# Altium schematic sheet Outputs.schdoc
size 345 x 187 mm
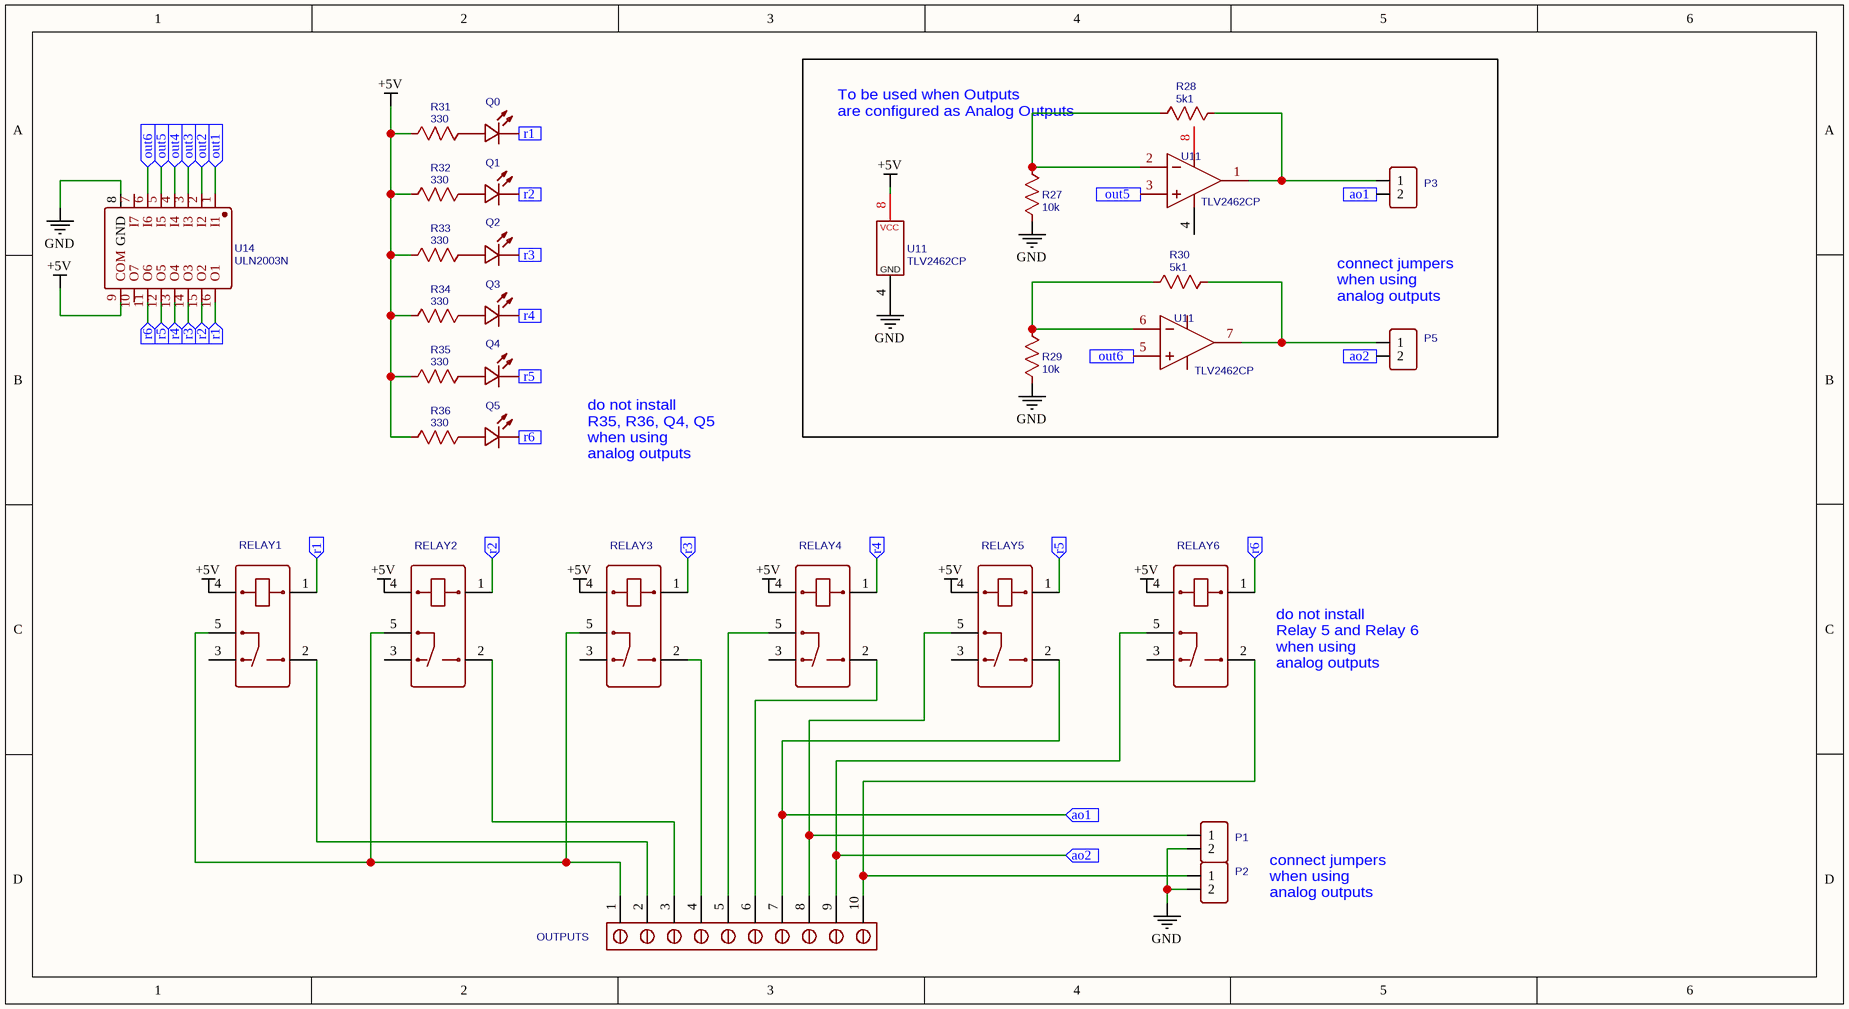
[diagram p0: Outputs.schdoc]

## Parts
(Parts that share a designator on the sheet are numbered #1, #2 ... from top to bottom, then left to right.)
OUTPUTS  TB008A-508-10BE  [TB008A-508-10BE]  (value not drawn)
P1  Header-Female-2.54_1x2  [HDR-1X2/2.54]  (value not drawn)
P2  Header-Female-2.54_1x2  [HDR-1X2/2.54]  (value not drawn)
P3  Header-Female-2.54_1x2  [HDR-1X2/2.54]  (value not drawn)
P5  Header-Female-2.54_1x2  [HDR-1X2/2.54]  (value not drawn)
Q0  204-10SURD/S530-A3  [LED-3MM/2.54]  (value not drawn)
Q1  204-10SURD/S530-A3  [LED-3MM/2.54]  (value not drawn)
Q2  204-10SURD/S530-A3  [LED-3MM/2.54]  (value not drawn)
Q3  204-10SURD/S530-A3  [LED-3MM/2.54]  (value not drawn)
Q4  204-10SURD/S530-A3  [LED-3MM/2.54]  (value not drawn)
Q5  204-10SURD/S530-A3  [LED-3MM/2.54]  (value not drawn)
R27  10k  [AXIAL-0.3]
R28  5k1  [AXIAL-0.3]
R29  10k  [AXIAL-0.3]
R30  5k1  [AXIAL-0.3]
R31  330  [AXIAL-0.3]
R32  330  [AXIAL-0.3]
R33  330  [AXIAL-0.3]
R34  330  [AXIAL-0.3]
R35  330  [AXIAL-0.3]
R36  330  [AXIAL-0.3]
RELAY1  SRD-05VDC-SL-C  [RELAY-SL-SRD]  (value not drawn)
RELAY2  SRD-05VDC-SL-C  [RELAY-SL-SRD]  (value not drawn)
RELAY3  SRD-05VDC-SL-C  [RELAY-SL-SRD]  (value not drawn)
RELAY4  SRD-05VDC-SL-C  [RELAY-SL-SRD]  (value not drawn)
RELAY5  SRD-05VDC-SL-C  [RELAY-SL-SRD]  (value not drawn)
RELAY6  SRD-05VDC-SL-C  [RELAY-SL-SRD]  (value not drawn)
U11#1  TLV2462CP  [DIP-8_L9.8-W6.6-P2.54-LS7.6-BL]
U11#2  TLV2462CP  [DIP-8_LS7.62-L9.78-W6.60-PITCH2.54]
U11#3  TLV2462CP  [DIP-8_L9.8-W6.6-P2.54-LS7.6-BL]
U14  ULN2003N  [DIP-16_16P-LS7.62-L19.6-W7.7-P2.54-BL]

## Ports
ao1 (in), ao2 (in), out1 (in), out2 (in), out3 (in), out4 (in), out5 (in), out6 (in), r1 (in), r2 (in), r3 (in), r4 (in), r5 (in), r6 (in)

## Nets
+5V: R31.1 R32.1 R33.1 R34.1 R35.1 R36.1 RELAY1.4 RELAY2.4 RELAY3.4 RELAY4.4 RELAY5.4 RELAY6.4 U11#2.8(VCC) U14.9(COM)
GND: P1.2 P2.2 R27.1 R29.1 U11#2.4(GND) U14.8(GND)
ao1: OUTPUTS.7 P3.2 RELAY5.2 ; port ao1
ao2: OUTPUTS.9 P5.2 RELAY6.5 ; port ao2
out1: U14.1(I1) ; port out1
out2: U14.2(I2) ; port out2
out3: U14.3(I3) ; port out3
out4: U14.4(I4) ; port out4
out5: U11#1.3(IN1(+)) U14.5(I5) ; port out5
out6: U11#3.5(IN2(+)) U14.6(I6) ; port out6
r1: Q0.2(K) RELAY1.1 U14.16(O1) ; port r1
r2: Q1.2(K) RELAY2.1 U14.15(O2) ; port r2
r3: Q2.2(K) RELAY3.1 U14.14(O3) ; port r3
r4: Q3.2(K) RELAY4.1 U14.13(O4) ; port r4
r5: Q4.2(K) RELAY5.1 U14.12(O5) ; port r5
r6: Q5.2(K) RELAY6.1 U14.11(O6) ; port r6
NetOUTPUTS_1: OUTPUTS.1 RELAY1.5 RELAY2.5 RELAY3.5
NetOUTPUTS_2: OUTPUTS.2 RELAY1.2
NetOUTPUTS_3: OUTPUTS.3 RELAY2.2
NetOUTPUTS_4: OUTPUTS.4 RELAY3.2
NetOUTPUTS_5: OUTPUTS.5 RELAY4.5
NetOUTPUTS_6: OUTPUTS.6 RELAY4.2
NetOUTPUTS_8: OUTPUTS.8 P1.1 RELAY5.5
NetOUTPUTS_10: OUTPUTS.10 P2.1 RELAY6.2
NetP3_1: P3.1 R28.1 U11#1.1(OUT1)
NetP5_1: P5.1 R30.1 U11#3.7(OUT2)
NetQ0_1: Q0.1(A) R31.2
NetQ1_1: Q1.1(A) R32.2
NetQ2_1: Q2.1(A) R33.2
NetQ3_1: Q3.1(A) R34.2
NetQ4_1: Q4.1(A) R35.2
NetQ5_1: Q5.1(A) R36.2
NetR27_2: R27.2 R28.2 U11#1.2(IN1(-))
NetR29_2: R29.2 R30.2 U11#3.6(IN2(-))

Not connected (* = marked no-connect by the designer): RELAY1 3; RELAY2 3; RELAY3 3; RELAY4 3; RELAY5 3; RELAY6 3; U11#1 4(GND) 8(VCC); U14 7(I7) 10(O7)

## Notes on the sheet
- (near U11#2) To be used when Outputs
  are configured as Analog Outputs
- (near P5) connect jumpers
  when using
  analog outputs
- do not install
  R35, R36, Q4, Q5
  when using
  analog outputs
- (near RELAY6) do not install
  Relay 5 and Relay 6
  when using
  analog outputs
- connect jumpers
  when using
  analog outputs

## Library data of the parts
OUTPUTS = TB008A-508-10BE: BOM_Manufacturer: CUI; Contributor: nexosrl
P1-P3 P5 = Header-Female-2.54_1x2: BOM_Manufacturer: BOOMELE; BOM_Manufacturer Part: 2.54-1*2PFemale
Q0-Q5 = 204-10SURD/S530-A3: BOM_Manufacturer: EVERLIGHT
R27 R29 = 10k: nameAlias: Value(Ω)
R28 R30 = 5k1: nameAlias: Value(Ω)
R31-R36 = 330: nameAlias: Value(Ω)
RELAY1-RELAY6 = SRD-05VDC-SL-C: BOM_Manufacturer: SONGLE
U11#1 = TLV2462CP: BOM_Manufacturer: TI; subpart_no: 2; Package Display: No
U11#2 = TLV2462CP: BOM_Manufacturer: TI; subpart_no: 1
U11#3 = TLV2462CP: BOM_Manufacturer: TI; subpart_no: 3; Package Display: No
U14 = ULN2003N: BOM_Manufacturer: HGSEMI; Contributor: LCSC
